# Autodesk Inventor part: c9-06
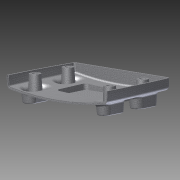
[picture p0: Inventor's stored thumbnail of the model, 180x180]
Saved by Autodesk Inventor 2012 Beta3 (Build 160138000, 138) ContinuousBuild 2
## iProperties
Created: 2010-12
Part Number: c9-06
Material: Default
Document SubType Name: Modeling
Designer: Beta-8540w
Density: 1 g/cm^3
Author: Beta-8540w
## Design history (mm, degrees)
sketch "Sketch1"
  geometry: L1 (-60, -12)-(60, -12); L2 (60, -12)-(60, 12); L3 (60, 12)-(-60, 12); L4 (-60, 12)-(-60, -12); A1 r 350 centre (0, -332.819) between (60, 12) and (-60, 12); A2 r 350 centre (0, 332.819) between (-60, -12) and (60, -12); 3 further points
  constraints: 8 end point, 4 point on circle, 2 centre point, 2 midpoint, 2 parallel, 1 equal radius, 1 horizontal, 1 horizontal alignment, 1 perpendicular, 1 vertical alignment
  dimensions: "d0" = 120 distance of L3.end L2.end; "d1" = 24 distance of L2.end L1.end; "d2" = 350 radius of A1
workplane "Work Plane4"
sketch "Sketch5"
  geometry: L1 (-60, 12)-(-60, -12) reference; L2 (60, -12)-(60, 12) reference; L3 (-58, 10.314)-(-58, -10.314); L4 (58, -10.314)-(58, 10.314); A1 r 350 centre (0, 332.819) between (-60, -12) and (60, -12) reference; A2 r 350 centre (0, -332.819) between (60, 12) and (-60, 12) reference; A3 r 348 centre (0, 332.819) between (-58, -10.314) and (58, -10.314); A4 r 348 centre (0, -332.819) between (58, 10.314) and (-58, 10.314); 1 further point
  constraints: 4 end point, 4 point on circle, 2 centre point, 3 other
  dimensions: "d37" = 2 distance between parallel lines of L2 L4
sketch "Sketch6"
  geometry: L1 (-60, 0)-(60, 0); L2 (60, 0)-(58.843, 22.085); L3 (-60, 0)-(-58.779, 23.307); A1 r 691.758 centre (630.81, -36.204) between (-60, 0) and (-58, -100); A2 r 691.758 centre (-630.81, -36.204) between (58, -100) and (60, 0); 1 further point
  constraints: 6 end point, 4 point on circle, 2 centre point, 2 tangent, 1 horizontal
  dimensions: "d53" = 87 deg angle of L1 L3; "d54" = 87 deg angle of L1 L2 (= d53)
sketch "Sketch7"
  geometry: L1 (17.181, 0)-(12, 0) reference; L2 (15.181, -100)-(10.314, -100) reference; L3 (17.181, 0)-(16.768, 11.838); A1 r 911.322 centre (-893.585, -31.805) between (15.181, -100) and (17.181, 0); 1 further point
  constraints: 2 end point, 2 point on circle, 1 centre point, 1 tangent
  dimensions: "d56" = 88 deg angle of L1 L3
feature "LoftSrf2" sketch "Sketch5", "Sketch6", "Sketch7" dims "d57" = 0, "d58" = 90 deg, "d59" = 0, "d60" = 90 deg, "d61" = 0, "d62" = 90 deg, "d63" = 0, "d64" = 90 deg, "d65" = 0, "d66" = 90 deg
sketch "Sketch2"
  geometry: L1 (-75, -16)-(75, -16); L2 (-75, -60)-(75, -60); A1 r 183.781 centre (0, -183.781) between (75, -16) and (-75, -16); 2 further points
  constraints: 4 end point, 3 point on circle, 1 centre point, 1 coincident, 1 horizontal, 1 parallel
  dimensions: "d5" = 16 distance from line of point (0, 0) L1; "d7" = 60 distance from line of point (0, 0) L2; "d55" = 150 distance of L1.start L1.end
feature "RevolutionSrf1" sketch "Sketch2" dims angle "d8" = 40 deg
patch "Boundary Patch1" dims "d13" = 0, "d67" = 0, "d68" = 0, "d69" = 0, "d70" = 0
workplane "Work Plane1"
sketch "Sketch3"
  geometry: L1 (52, -85)-(52, -73); L2 (38, -73)-(38, -85); A1 r 7 centre (45, -73) between (52, -73) and (38, -73); A2 r 7 centre (45, -85) between (38, -85) and (52, -85); 1 further point
  constraints: 4 end point, 4 point on circle, 4 tangent, 2 centre point, 1 parallel, 1 vertical
  dimensions: "d15" = 12 distance of L1.start L1.end; "d16" = 7 radius of A1; "d50" = 45 horizontal distance of A1.centre point (0, 0); "d51" = 85 vertical distance of point (0, 0) A2.centre
extrude_surface "ExtrusionSrf2" sketch "Sketch3" dims "d19" = 14, "d20" = 5 deg
pattern_linear "Rectangular Pattern1" dims "d23" = 90
workplane "Work Plane2"
feature "Sculpt1"
sketch "Sketch4"
  geometry: L1 (-24.5, 6)-(24.5, 6); L2 (27.5, 3)-(27.5, -3); L3 (24.5, -6)-(-24.5, -6); L4 (-27.5, -3)-(-27.5, 3); A1 r 3 centre (-24.5, 3) between (-24.5, 6) and (-27.5, 3); A2 r 3 centre (24.5, 3) between (27.5, 3) and (24.5, 6); A3 r 3 centre (24.5, -3) between (24.5, -6) and (27.5, -3); A4 r 3 centre (-24.5, -3) between (-27.5, -3) and (-24.5, -6); 6 further points
  constraints: 8 end point, 8 point on circle, 8 tangent, 6 point on line, 4 centre point, 3 equal radius, 2 midpoint, 2 parallel, 1 horizontal, 1 horizontal alignment, 1 perpendicular, 1 vertical alignment
  dimensions: "d28" = 55 distance of point (27.5, -6) point (-27.5, -6); "d29" = 12 distance of point (27.5, 6) point (27.5, -6); "d30" = 3 radius of A1
extrude_surface "ExtrusionSrf6" sketch "Sketch4" dims "d31" = 14, "d32" = 45 deg
patch "Boundary Patch2" dims "d33" = 0, "d34" = 0
fillet "Fillet1" dims "d79" = 4, "d80" = 3, "d81" = 1
feature "Sculpt2"
node "Splitting Plane 1"
shell "Shell1" dims "d83" = 2
split "Split1"
  body "Solid1"
feature "Lip1" dims "d149" = 1, "d150" = 1, "d151" = 0, "d152" = 0, "d153" = 0, "d154" = 0
feature "Lip2" dims "d155" = 1, "d156" = 1, "d157" = 0, "d158" = 0, "d159" = 0, "d160" = 0.5
split "Split3"
  node "Back"
sketch "Sketch9"
  geometry: L1 (50.167, -73)-(50.167, -85) reference; L2 (39.833, -85)-(39.833, -73) reference; L3 (45, -73)-(45, -85); L4 (45, -85)-(39.833, -85); A1 r 5.167 centre (45, -73) between (50.167, -73) and (39.833, -73) reference; A2 r 5.167 centre (45, -85) between (39.833, -85) and (50.167, -85) reference; 5 further points
  constraints: 4 end point, 1 horizontal, 1 midpoint, 1 parallel, 1 perpendicular, 1 vertical, 3 other
  dimensions: "d86" = 90 distance of point (45, -79) point (-45, -79); "d89" = 40 distance of point (45, -79) point (45, -39)
  node "Projected Loop1"
feature "Boss1" dims "d92" = 0, "d93" = 0, "d94" = 7, "d95" = 2, "d96" = 0.5, "d97" = 6, "d98" = 1.25, "d99" = 3.5, "d100" = 2.5 deg, "d101" = 2.5 deg, "d102" = 2.5 deg, "d103" = 2.5 deg, "d104" = 90 deg, "d107" = 2, "d108" = 2, "d109" = 10, "d110" = 0, "d111" = 10 deg, "d112" = 2.5 deg, "d113" = 0, "d114" = 0, "d115" = 0, "d116" = 360 deg
feature "Boss2" dims "d117" = 3, "d118" = 0, "d119" = 6, "d120" = 3, "d121" = 9.5, "d122" = 2 deg, "d123" = 1 deg, "d126" = 2, "d127" = 2, "d128" = 10, "d129" = 0, "d130" = 10 deg, "d131" = 2.5 deg, "d132" = 0, "d133" = 0, "d134" = 0, "d135" = 360 deg
workplane "Work Plane6"
sketch "Sketch10"
  geometry: L1 (24, -85)-(-24, -85); L2 (-30, -79)-(-30, -51); L3 (-24, -45)-(24, -45); L4 (30, -51)-(30, -79); L5 (54.344, -100)-(-54.344, -100) reference; A1 r 6 centre (-24, -51) between (-24, -45) and (-30, -51); A2 r 6 centre (24, -51) between (30, -51) and (24, -45); A3 r 6 centre (24, -79) between (24, -85) and (30, -79); A4 r 6 centre (-24, -79) between (-30, -79) and (-24, -85); 5 further points
  constraints: 8 end point, 8 point on circle, 8 tangent, 6 point on line, 4 centre point, 3 equal radius, 2 parallel, 1 horizontal, 1 midpoint, 1 perpendicular, 1 vertical alignment
  dimensions: "d137" = 60 distance of point (-30, -45) point (30, -45); "d138" = 40 distance of point (-30, -85) point (-30, -45); "d139" = 15 distance between parallel lines of L5 L1; "d141" = 6 radius of A2
feature "Rest1" sketch "Sketch10" dims "d142" = 5, "d143" = 0, "d144" = 0, "d145" = 0, "d146" = 2 deg, "d147" = 2 deg, "d148" = 2
body "Srf2"
body "Srf3"
body "Srf4"
body "Srf5"
body "Srf6"
body "Srf7"
body "Srf8"
body "Srf9"
body "Srf11"
feature "Stitch Surface1"
body "Srf12"
extrude_surface "ExtrusionSrf3"
extrude_surface "ExtrusionSrf4"
extrude_surface "ExtrusionSrf5"
node "Front"
node "Back - Top"
node "Back - Bottom"
other parameters: "d14" = -24, "d52" = -6
